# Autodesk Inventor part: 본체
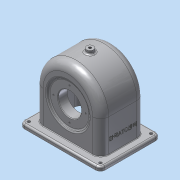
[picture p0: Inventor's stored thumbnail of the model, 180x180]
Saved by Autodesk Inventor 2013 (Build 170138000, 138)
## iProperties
Created: 2016-01
Part Number: 본체
Material: 알루미늄 6061
Document SubType Name: Modeling
Designer: Administrator
Mass: 874.696 g
Surface Area: 1049.39 cm^2
Volume: 322.766 cm^3
Density: 2.71 g/cm^3
Author: Administrator
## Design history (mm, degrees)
sketch "스케치1"
  geometry: L1 (-52, 70)-(52, 70); L2 (52, 70)-(52, -70); L3 (52, -70)-(-52, -70); L4 (-52, -70)-(-52, 70); 3 further points
  constraints: 8 end point, 2 midpoint, 2 parallel, 1 horizontal, 1 horizontal alignment, 1 perpendicular, 1 vertical alignment
  dimensions: "d0" = 104 distance of L1.start L1.end; "d2" = 140 distance of L1.end L2.end
extrude "돌출1" new body sketch "스케치1" distance "d3" = 7; taper "d4" = 0 deg
sketch "스케치2"
  geometry: L1 (-70, 0)-(70, 0) reference; L2 (-70, 0)-(-70, 7) reference; L3 (70, 7)-(-70, 7) reference; L4 (70, 0)-(70, 7) reference; L5 (-57, 64)-(-57, 0); L6 (57, 64)-(57, 0); L7 (-57, 0)-(57, 0); A1 r 57 centre (0, 64) between (-57, 64) and (57, 64); 2 further points
  constraints: 6 end point, 2 perpendicular, 2 point on circle, 2 point on line, 2 tangent, 1 centre point, 1 collinear, 1 midpoint, 1 vertical alignment
  dimensions: "d5" = 114 diameter of A1; "d7" = 64 distance of A1.centre point (0, 0)
  node "투영된 루프1"
extrude "돌출2" join sketch "스케치2" stored distance "d8" = 77; taper "d9" = 0 deg
sketch "스케치5"
  geometry: L1 (-57, 7)-(57, 7) reference; L2 (-57, 7)-(-57, 64) reference; L3 (57, 64)-(57, 7) reference; L4 (-70, 0)-(70, 0) reference; L5 (-70, 0)-(-70, 7) reference; L6 (70, 7)-(-70, 7) reference; L7 (70, 0)-(70, 7) reference; L8 (-51, 64)-(-51, 0); L9 (51, 64)-(51, 0); L10 (-51, 0)-(51, 0); A1 r 57 centre (0, 64) between (57, 64) and (-57, 64) reference; A2 r 51 centre (0, 64) between (51, 64) and (-51, 64); 1 further point
  constraints: 6 end point, 2 perpendicular, 2 point on circle, 2 point on line, 2 tangent, 1 centre point, 1 coincident, 1 parallel
  dimensions: "d12" = 102 diameter of A2
extrude "돌출3" cut sketch "스케치5" stored distance "d14" = 67; taper "d15" = 0 deg
sketch "스케치6"
  geometry: L1 (-38.5, 121)-(-38.5, 64) reference; L2 (-38.5, 64)-(-38.5, 7) reference; L3 (-33.5, 64)-(-33.5, 0) reference; L4 (-33.5, 115)-(-33.5, 64) reference; L5 (38.5, 64)-(38.5, 121) reference; L6 (38.5, 121)-(-38.5, 121) reference; L7 (33.5, 64)-(33.5, 115) reference; L8 (33.5, 115)-(-33.5, 115) reference; L9 (33.5, 0)-(33.5, 64) reference; L10 (38.5, 7)-(38.5, 64) reference; L11 (-72.8, 0)-(72.8, 0) reference; L12 (52, 7)-(-52, 7) reference; L13 (52, 0)-(52, 7) reference; L14 (-52, 0)-(-52, 7) reference; L15 (-38.5, 60)-(38.5, 60); L16 (-19.5, 60)-(-19.5, 88); L17 (-19.5, 88)-(-38.5, 103.943); L18 (-38.5, 60)-(-19.5, 60); L19 (-38.5, 103.943)-(-38.5, 60); 1 further point
  constraints: 10 end point, 4 point on line, 2 collinear, 2 perpendicular
  dimensions: "d16" = 60 distance from line of L11 L15.start; "d17" = 50 deg angle of L17 L16; "d18" = 28 distance of L16.start L16.end; "d19" = 19 distance between parallel lines of L19 L16
revolve "회전1" stored, may be unused: angle "d20" = 90 deg
sketch "스케치9"
  geometry: L1 (-38.5, 64)-(-38.5, 7) reference; L2 (-52, 0)-(52, 0) reference; L3 (-52, 0)-(-52, 7) reference; L4 (52, 7)-(-52, 7) reference; L5 (52, 0)-(52, 7) reference; L6 (38.5, 7)-(38.5, 64) reference; L7 (38.5, 64)-(38.5, 121) reference; L8 (38.5, 121)-(-38.5, 121) reference; L9 (-33.5, 99.747)-(-33.5, 20.253) reference; L10 (-19.5, 32)-(-19.5, 88) reference; L11 (-33.5, 99.747)-(-33.5, 20.253) reference; L12 (-33.5, 99.747)-(-19.5, 88) reference; L13 (33.5, 0)-(-33.5, 0) reference; L14 (33.5, 0)-(33.5, 64) reference; L15 (-33.5, 64)-(33.5, 64) reference; L16 (-33.5, 64)-(-33.5, 0) reference; L17 (-33.5, 20.253)-(-19.5, 32) reference; L18 (-38.5, 121)-(-38.5, 64) reference; L19 (-38.5, 60)-(38.5, 60); L20 (-35.5, 94.899)-(-35.5, 60); L21 (-38.5, 97.416)-(-35.5, 94.899); L22 (-35.5, 60)-(-38.5, 60); L23 (-38.5, 60)-(-38.5, 97.416); 1 further point
  constraints: 10 end point, 4 point on line, 2 collinear, 2 perpendicular, 1 parallel
  dimensions: "d23" = 60 vertical distance of L2.start L19.start; "d25" = 3 distance between parallel lines of L18 L20; "d26" = 5 distance between parallel lines of L12 L21
revolve "회전2" sketch "스케치9" stored, may be unused: angle "d27" = 90 deg
node "작업 평면1"
sketch "스케치11"
  geometry: C1 r 6 at (0, 0); 1 further point
  constraints: 1 centre point, 1 coincident
  dimensions: "d29" = 12 diameter of C1
extrude "돌출4" join sketch "스케치11" stored distance "d30" = 67; taper "d31" = 0 deg
sketch "스케치12"
  geometry: C1 r 31 at (64, 0); A1 r 57 centre (64, 0) between (64, -57) and (64, 57) reference; 1 further point
  constraints: 1 centre point, 1 coincident
  dimensions: "d32" = 62 diameter of C1
extrude "돌출5" join sketch "스케치12" distance "d33" = 10; taper "d34" = 0 deg
sketch "스케치13"
  geometry: C1 r 31 at (0, 0) reference; C2 r 20 at (0, 0); 1 further point
  constraints: 1 centre point, 1 coincident
  dimensions: "d35" = 40 diameter of C2
extrude "돌출6" cut sketch "스케치13" distance "d36" = 15; taper "d37" = 0 deg
sketch "스케치14" dims "d38" = 48
  geometry: C1 r 31 at (0, 0) reference; 3 further points
  constraints: 2 horizontal alignment, 1 coincident, 2 other
hole "구멍1" sketch "스케치14" at (24, 0) diameter "d39" = 2.459; stored, may be unused: countersink angle "d43" = 90 deg, drill point angle "d45" = 118 deg; dims "d40" = 6, "d41" = 4, "d42" = 2, "d44" = 8
sketch "스케치20"
  geometry: C1 r 28 at (0, 0) reference; C2 r 20 at (0, 0); 1 further point
  constraints: 1 centre point, 1 coincident
  dimensions: "d61" = 40 diameter of C2
extrude "돌출7" cut sketch "스케치20" distance "d62" = 19; taper "d63" = 0 deg
hole "구멍3" diameter "d66" = 4.459; stored, may be unused: countersink angle "d70" = 90 deg, drill point angle "d72" = 118 deg; dims "d64" = 10, "d65" = 10, "d67" = 20, "d68" = 4, "d69" = 2, "d71" = 9
sketch "스케치21"
  geometry: L1 (77, -15.584)-(77, -90.416) reference; L2 (0, 0)-(0, -57) reference; L3 (77, -57)-(77, 0) reference; L4 (90.5, 7)-(-13.5, 7) reference; L5 (90.5, 7)-(90.5, 0) reference; L6 (-13.5, 0)-(90.5, 0) reference; L7 (-13.5, 7)-(-13.5, 0) reference; L8 (63.387, -26.602)-(13.613, -26.602); L9 (13.613, -26.602)-(13.613, -19.398); L10 (13.613, -19.398)-(63.387, -19.398); L11 (63.387, -19.398)-(63.387, -26.602); 4 further points
  constraints: 2 midpoint, 1 horizontal alignment, 1 vertical alignment, 2 other
  dimensions: "d74" = 38.5 distance from line of point (38.5, -23) L3; "d75" = 30 distance from line of L4 point (38.5, -23)
feature "엠보싱1" sketch "스케치21" dims "d0" = 104, "d2" = 140, "d76" = 0.5, "d77" = 0
sketch "스케치22"
  geometry: L1 (-33.5, 51)-(-33.5, -51) reference; L2 (-33.5, -51)-(33.5, -51) reference; L3 (33.5, -51)-(33.5, 51) reference; L4 (33.5, 51)-(-33.5, 51) reference; L5 (-52, 70)-(52, 70) reference; L6 (52, 70)-(52, -70) reference; L7 (52, -70)-(-52, -70) reference; L8 (-52, -70)-(-52, 70) reference; 5 further points
  constraints: 2 horizontal alignment, 2 vertical alignment
  dimensions: "d78" = 8 distance from line of L6 point (44, -62); "d79" = 44 horizontal distance of point (0, 0) point (-44, -62); "d80" = 8 distance from line of point (-44, -62) L7; "d81" = 124 distance of point (-44, 62) point (-44, -62)
hole "구멍4" sketch "스케치22" at (44, -62), (-44, -62), (-44, 62), (44, 62) diameter "d82" = 5; stored, may be unused: countersink angle "d86" = 90 deg, drill point angle "d88" = 118 deg; dims "d83" = 20, "d84" = 4, "d85" = 2, "d87" = 9
fillet "모깎기1" dims "d89" = 8
fillet "모깎기2" dims "d90" = 3
fillet "모깎기3" dims "d91" = 3
fillet "모깎기4" dims "d92" = 14
fillet "모깎기5" dims "d93" = 9
chamfer "모따기1" distance "d94" = 1; stored, may be unused: second distance "d95" = 2, angle "d96" = 45 deg
fillet "모깎기6" dims "d97" = 1
fillet "모깎기7" dims "d98" = 3
fillet "모깎기8" dims "d99" = 3
sketch "스케치25" dims "d101" = 56
  geometry: C1 r 21 at (-60, 0) reference; C2 r 33.5 at (-60, 0) reference; 3 further points
  constraints: 2 horizontal alignment, 1 coincident, 2 other
hole "구멍5" sketch "스케치25" at (-88, 0) diameter "d102" = 2.459; stored, may be unused: countersink angle "d106" = 90 deg, drill point angle "d108" = 118 deg; dims "d103" = 10, "d104" = 4, "d105" = 2, "d107" = 12
node "솔리드1"
pattern_circular "원형 패턴1" dims angle "d47" = 360 deg
pattern_circular "원형 패턴3" dims angle "d110" = 360 deg
node "투영된 루프3"
node "투영된 루프4"
node "투영된 루프6"
node "투영된 루프7"
node "투영된 루프8"
node "투영된 루프11"
node "투영된 루프12"
node "투영된 루프14"
other parameters: "d24" = 5, "d28" = 127
